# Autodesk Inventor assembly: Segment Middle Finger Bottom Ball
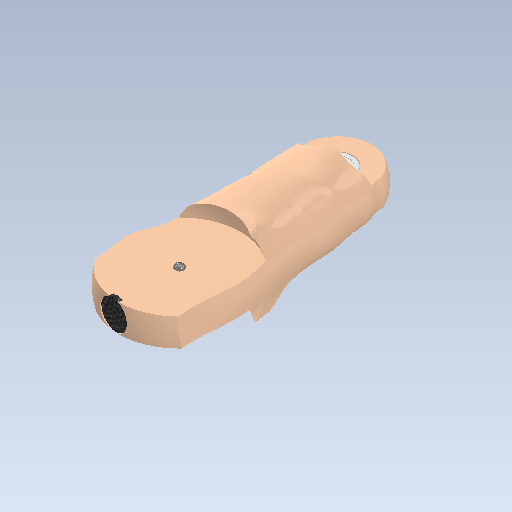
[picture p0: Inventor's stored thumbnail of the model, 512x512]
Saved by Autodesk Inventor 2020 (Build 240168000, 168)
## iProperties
Created: 2019-10
Part Number: Segment Middle Finger Bottom Ball
Document SubType Name: Assembly
Designer: yello
Author: yello
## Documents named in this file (8)
- D:\1-Cours-2021-22\1STI2D\ETLV\AI\Prototype 2 (Realistic Hand)\Segment Middle Finger Bottom Ball.iam
- D:\1-Cours-2021-22\1STI2D\ETLV\AI\Prototype 2 (Realistic Hand)\Segment Middle Finger Bottom.ipt
- D:\1-Cours-2021-22\1STI2D\ETLV\AI\Prototype 2 (Realistic Hand)\Push Part.ipt
- D:\1-Cours-2021-22\1STI2D\ETLV\AI\Prototype 2 (Realistic Hand)\Lock.ipt
- D:\1-Cours-2021-22\1STI2D\ETLV\AI\Prototype 2 (Realistic Hand)\Spring.ipt
- D:\1-Cours-2021-22\1STI2D\ETLV\AI\Prototype 2 (Realistic Hand)\Plug 4.ipt
- D:\1-Cours-2021-22\1STI2D\ETLV\AI\Prototype 2 (Realistic Hand)\Ball.ipt
- D:\1-Cours-2021-22\1STI2D\ETLV\AI\Prototype 2 (Realistic Hand)\Bearings.iam
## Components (8 placed, 7 different names)
1. Segment Middle Finger Bottom:1 — Mate:3, Mate:4, Mate:5, Mate:6, Mate:7, Mate:8, Mate:9, Mate:10, Flush:1
2. Push Part:1 — Mate:1, Mate:2, Mate:3
3. Lock:1 — Mate:1, Mate:2, Mate:4
4. Spring:1 — Mate:5
5. Plug 4:1 — Mate:6, Mate:7
6. Ball:1 — Mate:8
7. Ball:2 — Mate:9
8. Bearings:1 [sub-assembly] — Mate:10, Flush:1
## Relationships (11: Mate 10, Flush 1)
- Mate:1: Push Part:1 ↔ Lock:1
- Mate:2: Push Part:1 ↔ Lock:1
- Mate:3: Segment Middle Finger Bottom:1 ↔ Push Part:1
- Mate:4: Segment Middle Finger Bottom:1 ↔ Lock:1
- Mate:5: Segment Middle Finger Bottom:1 ↔ Spring:1
- Mate:6: Segment Middle Finger Bottom:1 ↔ Plug 4:1
- Mate:7: Segment Middle Finger Bottom:1 ↔ Plug 4:1
- Mate:8: Segment Middle Finger Bottom:1 ↔ Ball:1
- Mate:9: Segment Middle Finger Bottom:1 ↔ Ball:2
- Mate:10: Segment Middle Finger Bottom:1 ↔ Bearings:1
- Flush:1: Segment Middle Finger Bottom:1 ↔ Bearings:1
